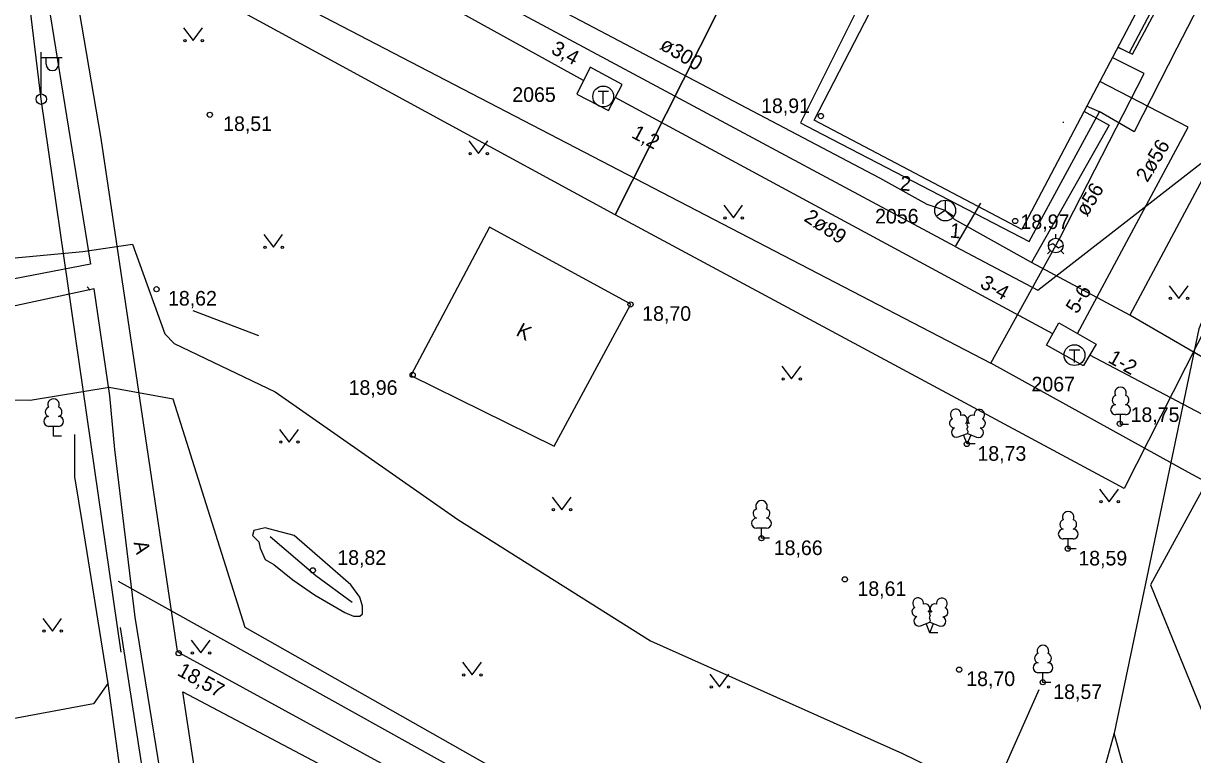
# Model space of a CAD drawing. Extents: x 713497 to 713863, y 6590062 to 6590327.
# Drawn here: x 713708.8 to 713764.9, y 6590112.4 to 6590147.5 of the extents above; entities that cross this region are included whole.
import ezdxf

# ---------------------------------------------------------------- set-up
doc = ezdxf.new("R2010")
doc.units = 0
for name, color, linetype in [('HALJASTUS', 7, 'Continuous'), ('HOONE', 7, 'Continuous'), ('HOONEDET', 7, 'Continuous'), ('KORGUS', 7, 'Continuous'), ('KPKAABEL', 7, 'Continuous'), ('MPKAABEL', 7, 'Continuous'), ('POST', 7, 'Continuous'), ('PUU', 7, 'Continuous'), ('SIKAEV', 7, 'Continuous'), ('SITRASS', 7, 'Continuous'), ('TEE', 7, 'Continuous'), ('TKAEV', 7, 'Continuous'), ('TORU NR', 7, 'Continuous'), ('TTRASS', 7, 'Continuous'), ('Слой 1', 7, 'Continuous')]:
    doc.layers.add(name, color=color, linetype=linetype)

msp = doc.modelspace()

# ---------------------------------------------------------------- linework, layer by layer
at = {"layer": 'HALJASTUS'}
for p, q in [((713716.517, 6590147.287), (713716.98, 6590146.68)), ((713716.98, 6590146.68), (713717.426, 6590147.287)), ((713730.197, 6590141.867), (713730.66, 6590141.26)), ((713730.66, 6590141.26), (713731.106, 6590141.867)), ((713742.417, 6590138.787), (713742.88, 6590138.18)), ((713742.88, 6590138.18), (713743.326, 6590138.787)), ((713720.357, 6590137.377), (713720.82, 6590136.77)), ((713720.82, 6590136.77), (713721.266, 6590137.377)), ((713763.777, 6590134.927), (713764.24, 6590134.32)), ((713764.24, 6590134.32), (713764.686, 6590134.927)), ((713745.207, 6590131.067), (713745.67, 6590130.46)), ((713745.67, 6590130.46), (713746.116, 6590131.067)), ((713721.117, 6590128.037), (713721.58, 6590127.43)), ((713721.58, 6590127.43), (713722.026, 6590128.037)), ((713734.187, 6590124.797), (713734.65, 6590124.19)), ((713734.65, 6590124.19), (713735.096, 6590124.797)), ((713760.447, 6590125.177), (713760.91, 6590124.57)), ((713760.91, 6590124.57), (713761.356, 6590125.177)), ((713709.757, 6590118.977), (713710.22, 6590118.37)), ((713710.22, 6590118.37), (713710.666, 6590118.977)), ((713716.877, 6590117.927), (713717.34, 6590117.32)), ((713717.34, 6590117.32), (713717.786, 6590117.927)), ((713729.887, 6590116.877), (713730.35, 6590116.27)), ((713730.35, 6590116.27), (713730.796, 6590116.877)), ((713741.757, 6590116.297), (713742.22, 6590115.69)), ((713742.22, 6590115.69), (713742.666, 6590116.297))]:
    msp.add_line(p, q, dxfattribs=at)
for points in [[(713720.12, 6590132.52), (713716.98, 6590133.73)], [(713711.29, 6590127.79), (713711.29, 6590125.77), (713711.66, 6590123.43), (713712.88, 6590115.85), (713713.92, 6590108.37)], [(713722.79, 6590120.11), (713724.24, 6590119.26), (713724.66, 6590119.08), (713724.97, 6590119.08), (713725.09, 6590119.2), (713725.09, 6590119.56), (713724.97, 6590119.99), (713724.54, 6590120.59), (713721.82, 6590122.95), (713720.91, 6590123.19), (713720.43, 6590123.32), (713719.88, 6590123.19), (713719.82, 6590122.95), (713720.12, 6590122.65), (713720.19, 6590122.35), (713720.43, 6590121.8), (713720.85, 6590121.56), (713721.76, 6590120.83), (713722.79, 6590120.11)], [(713724.6, 6590119.74), (713722.85, 6590121.02), (713720.67, 6590122.89)], [(713712.88, 6590115.85), (713712.19, 6590114.89), (713707.62, 6590114.04), (713699.86, 6590112.93)], [(713757.53, 6590115.56), (713751.81, 6590102.66)]]:
    msp.add_lwpolyline(points, dxfattribs=at)
for centre in [(713716.579, 6590146.68), (713717.408, 6590146.68), (713730.259, 6590141.26), (713731.088, 6590141.26), (713742.479, 6590138.18), (713743.308, 6590138.18), (713720.419, 6590136.77), (713721.248, 6590136.77), (713763.839, 6590134.32), (713764.668, 6590134.32), (713745.269, 6590130.46), (713746.098, 6590130.46), (713721.179, 6590127.43), (713722.008, 6590127.43), (713734.249, 6590124.19), (713735.078, 6590124.19), (713760.509, 6590124.57), (713761.338, 6590124.57), (713709.819, 6590118.37), (713710.648, 6590118.37), (713716.939, 6590117.32), (713717.768, 6590117.32), (713729.949, 6590116.27), (713730.778, 6590116.27), (713741.819, 6590115.69), (713742.648, 6590115.69)]:
    msp.add_circle(centre, 0.055, dxfattribs=at)
at = {"layer": 'HOONE'}
for p, q in [((713758.34, 6590137.2), (713758.34, 6590137.397)), ((713758.093, 6590136.603), (713757.953, 6590136.463)), ((713757.99, 6590136.848), (713758.201, 6590136.954)), ((713758.201, 6590136.954), (713758.479, 6590136.746)), ((713758.479, 6590136.746), (713758.69, 6590136.852)), ((713758.587, 6590136.603), (713758.727, 6590136.463))]:
    msp.add_line(p, q, dxfattribs=at)
for points in [[(713746.75, 6590142.86), (713753.996, 6590156.884), (713764.054, 6590151.55), (713756.708, 6590137.629), (713746.75, 6590142.86)], [(713719.11, 6590149.98), (713755.23, 6590131.21)], [(713755.23, 6590131.21), (713758.54, 6590137.21), (713762.58, 6590145.1), (713761.055, 6590145.867)], [(713756.708, 6590137.629), (713746.75, 6590142.86)], [(713731.18, 6590137.74), (713727.41, 6590130.63), (713734.28, 6590127.23), (713737.96, 6590134.05), (713731.18, 6590137.74)], [(713789.29, 6590112.76), (713764.71, 6590125.97), (713755.23, 6590131.21)]]:
    msp.add_lwpolyline(points, dxfattribs=at)
msp.add_circle((713758.34, 6590136.85), 0.35, dxfattribs=at)
at = {"layer": 'HOONEDET'}
for points in [[(713751.105, 6590152.755), (713753.739, 6590157.722), (713764.892, 6590151.807), (713761.864, 6590146.098), (713761.32, 6590146.37)], [(713751.105, 6590152.755), (713746.1, 6590142.73), (713746.77, 6590142.38), (713757.06, 6590137.04), (713760.44, 6590143.27), (713759.821, 6590143.53)], [(713758.7, 6590142.78), (713758.7, 6590142.73)]]:
    msp.add_lwpolyline(points, dxfattribs=at)
at = {"layer": 'KORGUS'}
for centre in [(713717.77, 6590143.12), (713747.08, 6590143.06), (713756.4, 6590138.03), (713715.22, 6590134.76), (713737.95, 6590134.03), (713727.5, 6590130.65), (713761.42, 6590128.31), (713754.08, 6590127.34), (713744.23, 6590122.82), (713758.92, 6590122.32), (713722.71, 6590121.28), (713748.23, 6590120.85), (713716.28, 6590117.31), (713753.71, 6590116.52), (713757.72, 6590115.92)]:
    msp.add_circle(centre, 0.125, dxfattribs=at)
at = {"layer": 'KPKAABEL'}
for points in [[(713794.45, 6590198.59), (713786.13, 6590180.02), (713781.379, 6590168.923), (713780.962, 6590168.239), (713779.091, 6590164.176), (713775.448, 6590156.503), (713774.002, 6590151.688), (713770.408, 6590144.999), (713769.646, 6590143.487), (713765.21, 6590132.86), (713761.14, 6590113.48)], [(713773.44, 6590139.89), (713762.88, 6590120.59), (713775.24, 6590090.28), (713794.548, 6590082.284), (713800.542, 6590079.311), (713832.311, 6590062.302)], [(713757.93, 6590103.87), (713750.44, 6590106.37), (713743.71, 6590104.81), (713719.46, 6590118.54), (713716.02, 6590129.49), (713712.95, 6590130.05)], [(713761.14, 6590113.48), (713759.78, 6590108.59), (713757.93, 6590103.87)], [(713762.81, 6590107.46), (713761.14, 6590113.48)]]:
    msp.add_lwpolyline(points, dxfattribs=at)
at = {"layer": 'MPKAABEL'}
for points in [[(713712.95, 6590130.05), (713709.16, 6590129.42), (713701.69, 6590129.47), (713690.5, 6590129.51), (713688.19, 6590129.12), (713683.66, 6590141.1), (713679.81, 6590148.4), (713679.37, 6590149.39), (713679.04, 6590150.26), (713678.83, 6590150.79), (713678.48, 6590151.44), (713677.98, 6590152.02), (713677.43, 6590152.31), (713676.95, 6590152.28), (713676.524, 6590152.014), (713670.183, 6590149.934), (713666.077, 6590148.723), (713655.565, 6590146.628), (713640.392, 6590143.766), (713637.411, 6590156.292), (713634.246, 6590158.892), (713632.822, 6590162.256), (713631.92, 6590167.25), (713628.288, 6590166.652)], [(713709.69, 6590143.87), (713708.98, 6590149.7), (713711.79, 6590156.14)], [(713753.52, 6590136.81), (713724.9, 6590152.17)], [(713753.52, 6590136.81), (713757.48, 6590134.71), (713769.123, 6590143.755), (713769.116, 6590143.758), (713771.25, 6590145.42), (713772.245, 6590144.971)], [(713713.52, 6590117.36), (713709.69, 6590143.87)], [(713754.73, 6590138.88), (713753.52, 6590136.81)], [(713706.02, 6590136.037), (713711.684, 6590136.564), (713714.061, 6590136.92), (713715.619, 6590132.628), (713716.068, 6590132.153), (713720.91, 6590129.844), (713729.671, 6590123.725), (713738.912, 6590117.901), (713750.996, 6590112.509), (713761.287, 6590107.48)], [(713713.37, 6590120.76), (713745.23, 6590103.02), (713745.42, 6590103.07)], [(713713.47, 6590118.54), (713716.57, 6590098.57)]]:
    msp.add_lwpolyline(points, dxfattribs=at)
at = {"layer": 'POST'}
for p, q in [((713709.69, 6590144.12), (713709.69, 6590146.12)), ((713709.69, 6590145.87), (713710.69, 6590145.87)), ((713709.917, 6590145.549), (713709.917, 6590145.87)), ((713710.529, 6590145.549), (713710.529, 6590145.87))]:
    msp.add_line(p, q, dxfattribs=at)
msp.add_circle((713709.69, 6590143.87), 0.25, dxfattribs=at)
msp.add_arc((713710.223, 6590145.549), 0.306, 180, 0, dxfattribs=at)
at = {"layer": 'PUU'}
for p, q in [((713761.69, 6590128.745), (713761.21, 6590128.745)), ((713761.45, 6590128.27), (713761.45, 6590128.745)), ((713710.52, 6590128.185), (713710.04, 6590128.185)), ((713710.28, 6590127.71), (713710.28, 6590128.185)), ((713761.83, 6590128.27), (713761.45, 6590128.27)), ((713710.66, 6590127.71), (713710.28, 6590127.71)), ((713753.66, 6590127.675), (713754.105, 6590127.85)), ((713754.1, 6590127.34), (713753.925, 6590127.78)), ((713754.1, 6590127.34), (713754.28, 6590127.78)), ((713754.105, 6590127.85), (713754.545, 6590127.67)), ((713754.48, 6590127.34), (713754.1, 6590127.34)), ((713744.47, 6590123.305), (713743.99, 6590123.305)), ((713744.23, 6590122.83), (713744.23, 6590123.305)), ((713744.61, 6590122.83), (713744.23, 6590122.83)), ((713759.18, 6590122.785), (713758.7, 6590122.785)), ((713758.94, 6590122.31), (713758.94, 6590122.785)), ((713759.32, 6590122.31), (713758.94, 6590122.31)), ((713751.86, 6590118.625), (713752.305, 6590118.8)), ((713752.3, 6590118.29), (713752.125, 6590118.73)), ((713752.3, 6590118.29), (713752.48, 6590118.73)), ((713752.305, 6590118.8), (713752.745, 6590118.62)), ((713752.68, 6590118.29), (713752.3, 6590118.29)), ((713757.97, 6590116.375), (713757.49, 6590116.375)), ((713757.73, 6590115.9), (713757.73, 6590116.375)), ((713758.11, 6590115.9), (713757.73, 6590115.9))]:
    msp.add_line(p, q, dxfattribs=at)
for points in [[(713754.105, 6590128.345), (713754.085, 6590128.27), (713754.085, 6590128.25), (713754.095, 6590128.22), (713754.115, 6590128.185), (713754.12, 6590128.165), (713754.105, 6590128.13), (713754.08, 6590128.08), (713754.075, 6590128.055), (713754.08, 6590128.04), (713754.09, 6590128.01), (713754.125, 6590127.95), (713754.13, 6590127.93), (713754.125, 6590127.91), (713754.11, 6590127.875), (713754.105, 6590127.85)], [(713752.305, 6590119.295), (713752.285, 6590119.22), (713752.285, 6590119.2), (713752.295, 6590119.17), (713752.315, 6590119.135), (713752.32, 6590119.115), (713752.305, 6590119.08), (713752.28, 6590119.03), (713752.275, 6590119.005), (713752.28, 6590118.99), (713752.29, 6590118.96), (713752.325, 6590118.9), (713752.33, 6590118.88), (713752.325, 6590118.86), (713752.31, 6590118.825), (713752.305, 6590118.8)]]:
    msp.add_lwpolyline(points, dxfattribs=at)
for centre, radius, start, end in [((713761.45, 6590129.79), 0.277, 332.5799, 207.4201), ((713710.28, 6590129.23), 0.277, 332.5799, 207.4201), ((713761.28, 6590129.443), 0.233, 109.0217, 253.1415), ((713761.62, 6590129.443), 0.233, 286.8508, 70.9859), ((713710.11, 6590128.883), 0.233, 109.0217, 253.1415), ((713710.45, 6590128.883), 0.233, 286.8508, 70.9859), ((713753.543, 6590128.754), 0.256, 111.5027, 232.5173), ((713753.543, 6590128.754), 0.256, 350.4856, 111.5002), ((713753.878, 6590128.504), 0.224, 308.5041, 111.5725), ((713754.341, 6590128.499), 0.225, 67.7016, 230.5126), ((713754.679, 6590128.745), 0.256, 67.6168, 188.6314), ((713754.679, 6590128.745), 0.256, 306.5997, 67.6143), ((713761.213, 6590128.982), 0.238, 90.0016, 269.3953), ((713761.687, 6590128.982), 0.238, 270.6047, 89.9984), ((713710.043, 6590128.422), 0.238, 90.0016, 269.3953), ((713710.517, 6590128.422), 0.238, 270.6047, 89.9984), ((713753.469, 6590128.343), 0.224, 111.4304, 274.4987), ((713754.104, 6590128.107), 0.237, 66.7655, 111.5015), ((713754.746, 6590128.333), 0.224, 264.6183, 67.6866), ((713753.574, 6590127.898), 0.237, 111.5014, 291.5004), ((713754.635, 6590127.89), 0.237, 247.6166, 67.6155), ((713744.23, 6590124.35), 0.277, 332.5799, 207.4201), ((713743.993, 6590123.542), 0.238, 90.0016, 269.3953), ((713744.06, 6590124.003), 0.233, 109.0217, 253.1415), ((713744.4, 6590124.003), 0.233, 286.8508, 70.9859), ((713744.467, 6590123.542), 0.238, 270.6047, 89.9984), ((713758.77, 6590123.483), 0.233, 109.0217, 253.1415), ((713758.94, 6590123.83), 0.277, 332.5799, 207.4201), ((713759.11, 6590123.483), 0.233, 286.8508, 70.9859), ((713758.703, 6590123.022), 0.238, 90.0016, 269.3953), ((713759.177, 6590123.022), 0.238, 270.6047, 89.9984), ((713751.743, 6590119.704), 0.256, 111.5027, 232.5173), ((713751.743, 6590119.704), 0.256, 350.4856, 111.5002), ((713752.879, 6590119.695), 0.256, 67.6168, 188.6314), ((713752.879, 6590119.695), 0.256, 306.5997, 67.6143), ((713751.669, 6590119.293), 0.224, 111.4304, 274.4987), ((713752.078, 6590119.454), 0.224, 308.5041, 111.5725), ((713752.304, 6590119.057), 0.237, 66.7655, 111.5015), ((713752.541, 6590119.449), 0.225, 67.7016, 230.5126), ((713752.946, 6590119.283), 0.224, 264.6183, 67.6866), ((713751.774, 6590118.848), 0.237, 111.5014, 291.5004), ((713752.835, 6590118.84), 0.237, 247.6166, 67.6155), ((713757.73, 6590117.42), 0.277, 332.5799, 207.4201), ((713757.56, 6590117.073), 0.233, 109.0217, 253.1415), ((713757.9, 6590117.073), 0.233, 286.8508, 70.9859), ((713757.493, 6590116.612), 0.238, 90.0016, 269.3953), ((713757.967, 6590116.612), 0.238, 270.6047, 89.9984)]:
    msp.add_arc(centre, radius, start, end, dxfattribs=at)
at = {"layer": 'SIKAEV'}
for p, q in [((713753.04, 6590139.03), (713753.04, 6590138.53)), ((713753.04, 6590138.53), (713752.625, 6590138.255)), ((713753.04, 6590138.53), (713753.455, 6590138.255))]:
    msp.add_line(p, q, dxfattribs=at)
msp.add_circle((713753.04, 6590138.53), 0.5, dxfattribs=at)
at = {"layer": 'SITRASS'}
for points in [[(713761.318, 6590146.366), (713762.03, 6590146.03), (713762.599, 6590147.099), (713773.56, 6590167.68), (713757.589, 6590176.783), (713720.92, 6590195.235), (713722.942, 6590199.176), (713727.49, 6590208.04), (713727.52, 6590208.2), (713727.47, 6590208.33), (713725.65, 6590209.17)], [(713863.358, 6590109.383), (713837.06, 6590123.42), (713818.31, 6590133.22), (713795.51, 6590145.62), (713774.46, 6590157.04), (713767.746, 6590144.461), (713761.9, 6590133.51)], [(713753.04, 6590138.53), (713752.18, 6590138.82), (713749.91, 6590140.08), (713728.55, 6590151.34), (713723.06, 6590154.35)], [(713735.37, 6590144.11), (713736.9, 6590143.32), (713737.55, 6590144.58), (713736.01, 6590145.4), (713735.37, 6590144.11)], [(713759.696, 6590143.293), (713760.91, 6590142.62), (713757.18, 6590136.04)], [(713757.18, 6590136.04), (713753.48, 6590138.1), (713753.04, 6590138.53)], [(713761.9, 6590133.51), (713757.18, 6590136.04)], [(713789.24, 6590117.86), (713783.55, 6590120.96), (713761.9, 6590133.51)]]:
    msp.add_lwpolyline(points, dxfattribs=at)
at = {"layer": 'TEE'}
for points in [[(713710.467, 6590174.389), (713711.174, 6590166.795), (713710.458, 6590154.269), (713712.543, 6590141.98), (713716.21, 6590117.41), (713716.46, 6590117.25), (713750.16, 6590098.82), (713790.169, 6590075.991)], [(713708.411, 6590135.253), (713698.461, 6590133.384), (713702.375, 6590138.709), (713709.41, 6590152.273), (713712.047, 6590135.954), (713708.411, 6590135.253)], [(713840.64, 6590113.44), (713767.635, 6590151.97), (713765.451, 6590148.839), (713764.143, 6590146.308), (713762.11, 6590142.3), (713760.42, 6590143.28)], [(713711.89, 6590134.88), (713712.03, 6590134.72)], [(713724.118, 6590062.302), (713723.44, 6590065.38), (713721.87, 6590070.76), (713721.55, 6590072.92), (713716.91, 6590102.31), (713714.19, 6590119.04), (713713.21, 6590127.08), (713712.97, 6590129.65), (713712.223, 6590134.78), (713701.682, 6590132.514), (713689.607, 6590129.871), (713687.975, 6590128.819), (713687.123, 6590127.269)], [(713725.436, 6590062.302), (713725.02, 6590064.58), (713723.58, 6590070.84), (713719.73, 6590093.93), (713718.29, 6590103.6), (713716.48, 6590115.46), (713731.16, 6590107.7), (713732.95, 6590106.76), (713749.2, 6590097.48), (713768.4, 6590086.99), (713789.423, 6590074.743), (713795.471, 6590071.359), (713795.686, 6590069.951), (713791.53, 6590062.302)]]:
    msp.add_lwpolyline(points, dxfattribs=at)
at = {"layer": 'TKAEV'}
for p, q in [((713736.39, 6590144.25), (713736.89, 6590144.25)), ((713736.64, 6590143.65), (713736.64, 6590144.25)), ((713758.99, 6590131.85), (713759.49, 6590131.85)), ((713759.24, 6590131.25), (713759.24, 6590131.85))]:
    msp.add_line(p, q, dxfattribs=at)
for centre in [(713736.64, 6590144), (713759.24, 6590131.6)]:
    msp.add_circle(centre, 0.5, dxfattribs=at)
at = {"layer": 'TTRASS'}
for points in [[(713735.69, 6590144.76), (713719.81, 6590153.56), (713711.69, 6590158.44)], [(713759.38, 6590132.64), (713764.69, 6590142.53), (713760.449, 6590144.72)], [(713758.2, 6590132.62), (713737.22, 6590143.95)], [(713757.9, 6590132.08), (713758.49, 6590133.15), (713760.28, 6590132.12), (713759.68, 6590131.1), (713759.64, 6590131.1), (713757.9, 6590132.08)], [(713793.78, 6590113.79), (713759.97, 6590131.6)]]:
    msp.add_lwpolyline(points, dxfattribs=at)
at = {"layer": 'Слой 1'}
for points in [[(713749.45, 6590162.59), (713737.22, 6590138.32), (713711.06, 6590152.57), (713722.66, 6590177.41)], [(713749.45, 6590162.59), (713773.95, 6590149.53), (713761.63, 6590125.2), (713737.22, 6590138.32)]]:
    msp.add_lwpolyline(points, close=True, dxfattribs=at)

# ---------------------------------------------------------------- texts
at = {"layer": 'HOONE'}
msp.add_text('K', height=0.7, rotation=332.0924, dxfattribs=at).set_placement((713732.409, 6590132.566))
at = {"layer": 'KORGUS'}
for s, p in [('18,91', (713744.212, 6590143.205)), ('18,51', (713718.412, 6590142.345)), ('18,97', (713756.653, 6590137.645)), ('18,62', (713715.768, 6590133.975)), ('18,70', (713738.511, 6590133.245)), ('18,96', (713724.43, 6590129.695)), ('18,75', (713761.933, 6590128.395)), ('18,73', (713754.586, 6590126.535)), ('18,66', (713744.82, 6590122.015)), ('18,82', (713723.888, 6590121.545)), ('18,59', (713759.426, 6590121.515)), ('18,61', (713748.832, 6590120.055)), ('18,70', (713754.051, 6590115.735)), ('18,57', (713758.223, 6590115.115))]:
    msp.add_text(s, height=0.7, dxfattribs=at).set_placement(p)
msp.add_text('18,57', height=0.7, rotation=331.1917, dxfattribs=at).set_placement((713716.164, 6590116.281))
at = {"layer": 'SIKAEV'}
for s, p in [('2065', (713732.28, 6590143.74)), ('2056', (713749.68, 6590137.91)), ('2067', (713757.18, 6590129.86))]:
    msp.add_text(s, height=0.7, dxfattribs=at).set_placement(p)
at = {"layer": 'TEE'}
msp.add_text('A', height=0.7, rotation=283.9574, dxfattribs=at).set_placement((713714.112, 6590122.613))
at = {"layer": 'TORU NR'}
for s, rotation, p in [('ø300', 328.9855, (713739.304, 6590146.303)), ('3,4', 331.919, (713734.093, 6590146.092)), ('1,2', 331.919, (713737.953, 6590142.052)), ('2ø56', 58.7707, (713762.736, 6590139.845)), ('2', 354.7103, (713750.851, 6590139.51)), ('ø56', 58.7707, (713759.841, 6590138.199)), ('2ø89', 326.5409, (713746.223, 6590138.067)), ('1', 354.7103, (713753.241, 6590137.24)), ('3-4', 330.7145, (713754.661, 6590134.873)), ('5-6', 57.8344, (713759.364, 6590133.537)), ('1-2', 330.7145, (713760.801, 6590131.283))]:
    msp.add_text(s, height=0.7, rotation=rotation, dxfattribs=at).set_placement(p)

doc.saveas('drawing.dxf')
